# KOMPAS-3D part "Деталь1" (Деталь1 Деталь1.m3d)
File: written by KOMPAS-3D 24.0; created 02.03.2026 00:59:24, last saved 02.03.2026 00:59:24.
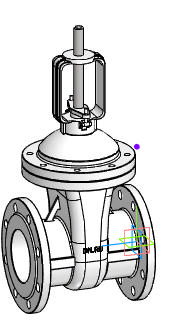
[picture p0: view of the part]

Document properties: Автор: R2D2; Полное имя файла: E:\Работа\Зайцев\GVWR3131M-2W-F-S Задвижка клиновая с выдвижным штоком DN.ru Ду50-200 Ру63\DN100\исходные материалы\Деталь1 Деталь1.m3d

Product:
- Body: Твердое тело1  | qty 1
- Part/product: Деталь1
    additional columns: Типовые

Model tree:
1. Твердое тело1  (labels: Твердое тело1)
2. Точка:1
     Y = 186.5; Координата Y = 186.5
